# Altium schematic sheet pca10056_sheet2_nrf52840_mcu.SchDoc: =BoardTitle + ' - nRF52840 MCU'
size A3; Organization: Nordic Semiconductor; DocumentNumber: 2; SheetNumber: 2; SheetTotal: 6; CompanyName: Nordic Semiconductor; DocumentSize: A3
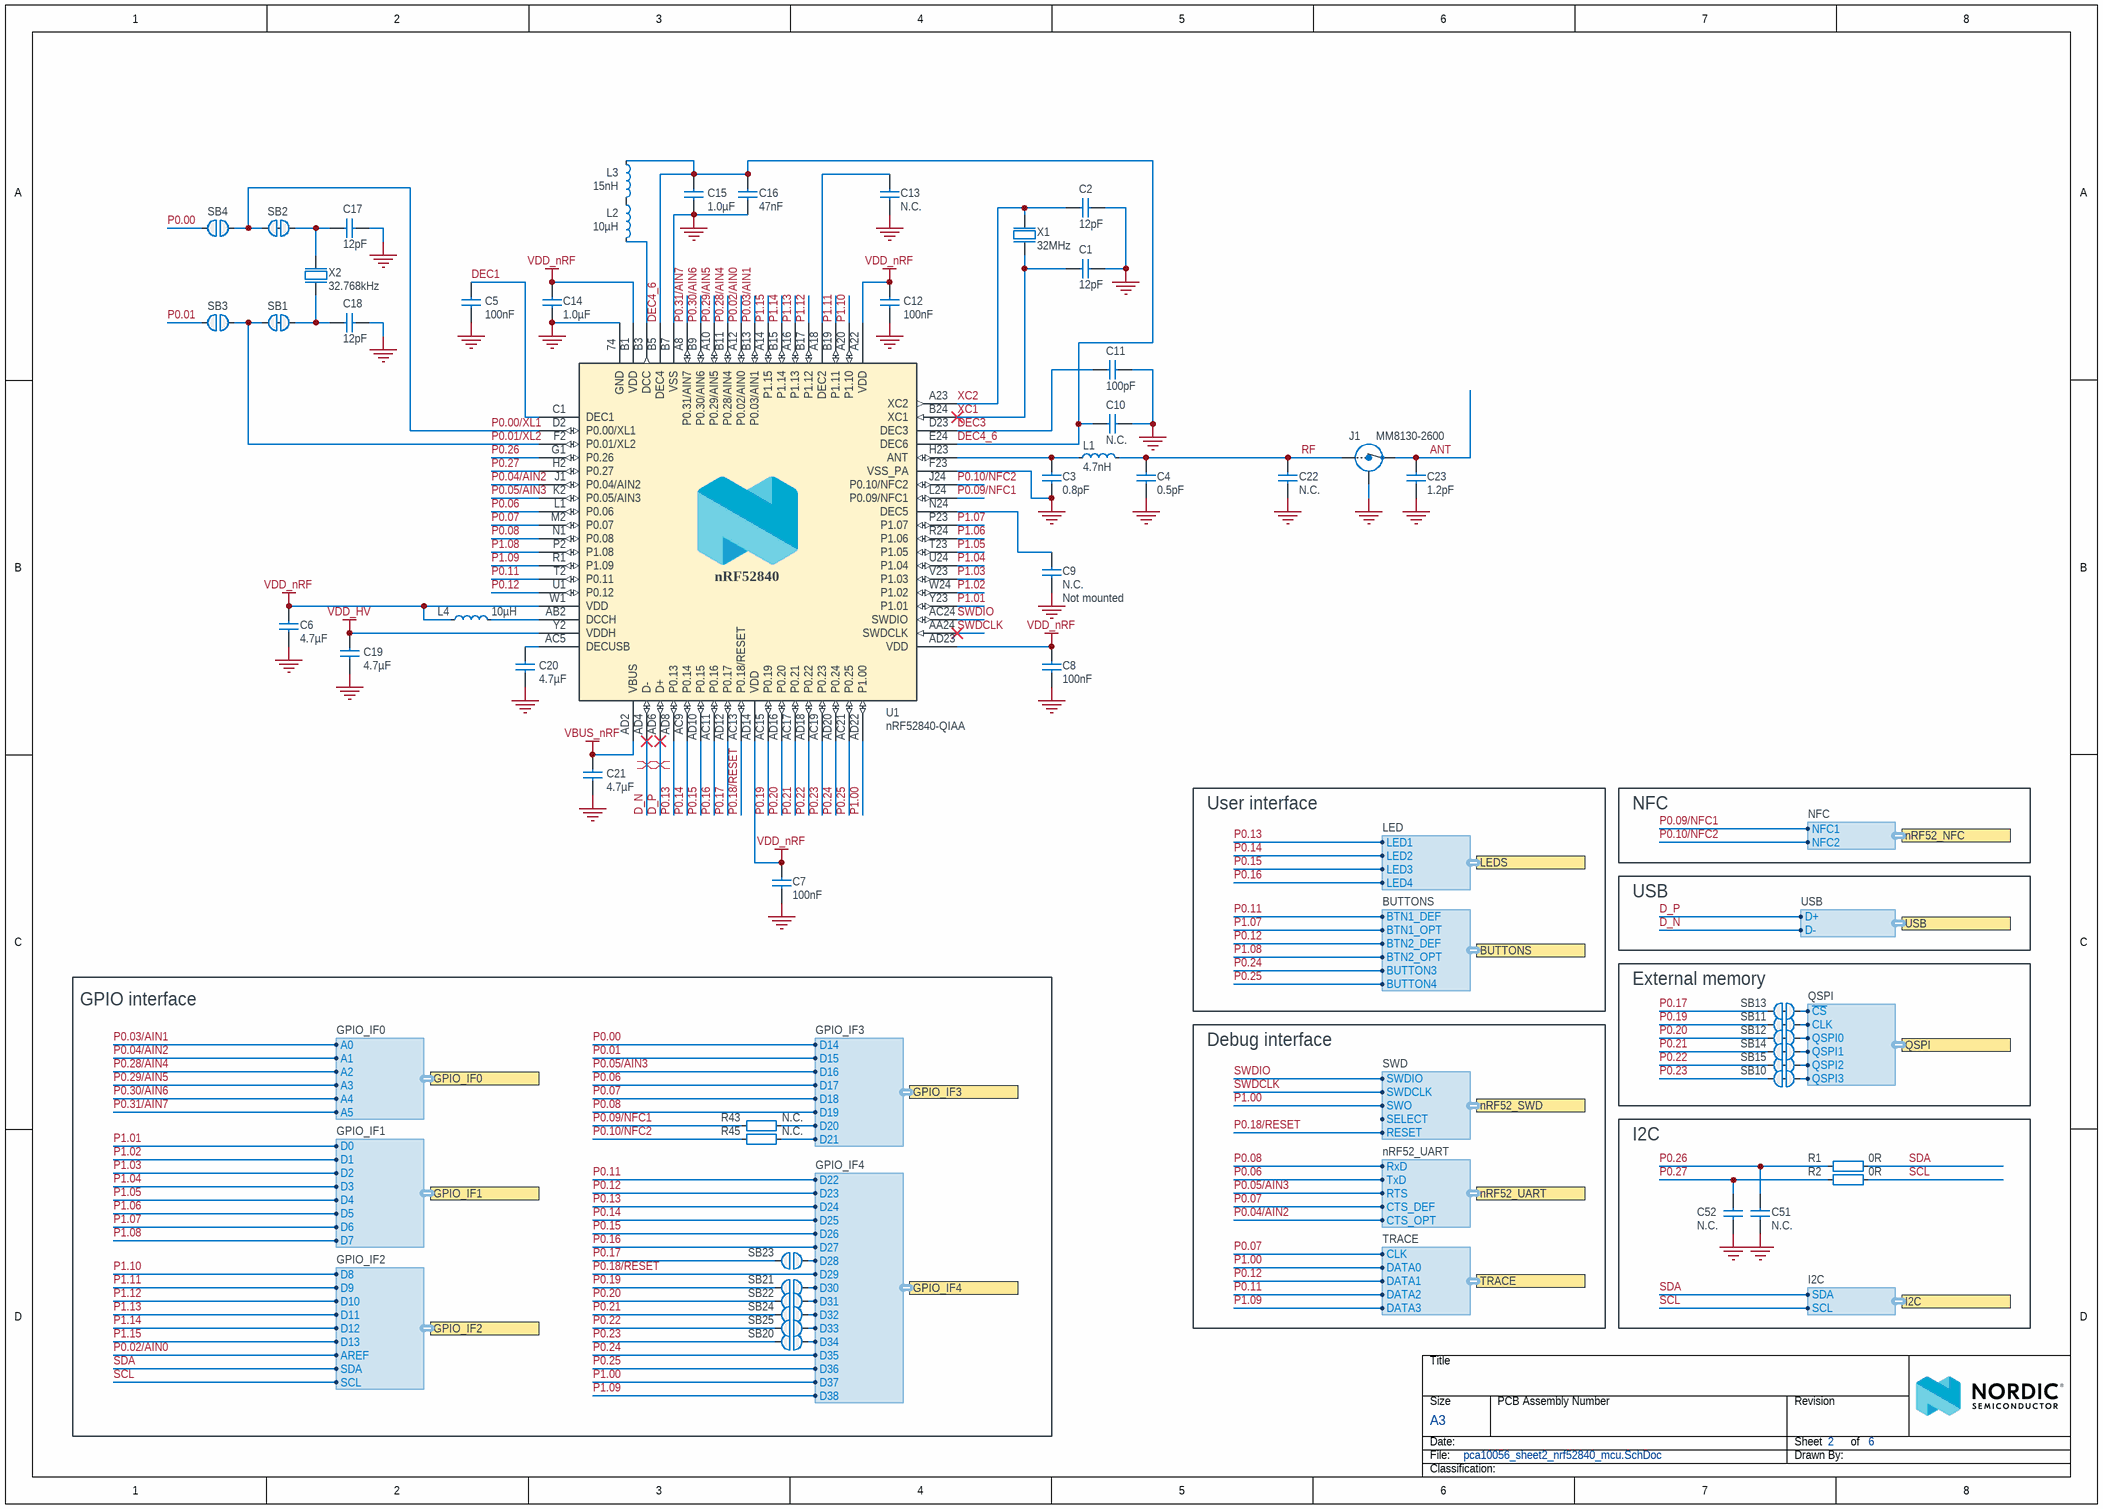
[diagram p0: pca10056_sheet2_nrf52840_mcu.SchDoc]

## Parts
C1  12pF  [CAPC1005X04L]
C2  12pF  [CAPC1005X04L]
C3  0.8pF  [CAPC1005X04L]
C4  0.5pF  [CAPC1005X04L]
C5  100nF  [CAPC1005X04L]
C6  4.7µF  [CAPC1608X06L]
C7  100nF  [CAPC1005X04L]
C8  100nF  [CAPC1005X04L]
C9  N.C.  Assembly: Not mounted  [CAPC1005X04L_NC]
C10  N.C.  [CAPC1005X04L_NC]
C11  100pF  [CAPC1005X04L]
C12  100nF  [CAPC1005X04L]
C13  N.C.  [CAPC1005X04L_NC]
C14  1.0µF  [CAPC1608X06L]
C15  1.0µF  [CAPC1608X06L]
C16  47nF  [CAPC1005X04L]
C17  12pF  [CAPC1005X04L]
C18  12pF  [CAPC1005X04L]
C19  4.7µF  [CAPC1608X06L]
C20  4.7µF  [CAPC1608X06L]
C21  4.7µF  [CAPC1608X06L]
C22  N.C.  [CAPC1005X04L_NC]
C23  1.2pF  [CAPC1005X04L]
C51  N.C.  [CAPC0603X03L_C_NC]
C52  N.C.  [CAPC0603X03L_C_NC]
J1  MM8130-2600  [COAXIAL-SWF]
L1  4.7nH  [INDC1005X04L]
L2  10µH  [INDC1608X06L]
L3  15nH  [INDC1005X04L]
L4  10µH  [INDC1608X06L]
R1  0R  [RESC0603X03L_C]
R2  0R  [RESC0603X03L_C]
R43  N.C.  [RESC1005X04L_NC]
R45  N.C.  [RESC1005X04L_NC]
SB1  Solderbridge  [Solderbridge_Shorted]  (value not drawn)  (net tie, no BOM)
SB2  Solderbridge  [Solderbridge_Shorted]  (value not drawn)  (net tie, no BOM)
SB3  Solderbridge  [Solderbridge]  (value not drawn)  (no BOM)
SB4  Solderbridge  [Solderbridge]  (value not drawn)  (no BOM)
SB10  Solderbridge  [Solderbridge_Shorted]  (value not drawn)  (net tie, no BOM)
SB11  Solderbridge  [Solderbridge_Shorted]  (value not drawn)  (net tie, no BOM)
SB12  Solderbridge  [Solderbridge_Shorted]  (value not drawn)  (net tie, no BOM)
SB13  Solderbridge  [Solderbridge_Shorted]  (value not drawn)  (net tie, no BOM)
SB14  Solderbridge  [Solderbridge_Shorted]  (value not drawn)  (net tie, no BOM)
SB15  Solderbridge  [Solderbridge_Shorted]  (value not drawn)  (net tie, no BOM)
SB20  Solderbridge  [Solderbridge]  (value not drawn)  (no BOM)
SB21  Solderbridge  [Solderbridge]  (value not drawn)  (no BOM)
SB22  Solderbridge  [Solderbridge]  (value not drawn)  (no BOM)
SB23  Solderbridge  [Solderbridge]  (value not drawn)  (no BOM)
SB24  Solderbridge  [Solderbridge]  (value not drawn)  (no BOM)
SB25  Solderbridge  [Solderbridge]  (value not drawn)  (no BOM)
U1  nRF52840-QIAA  [AQFN50P700X700X85_HS-74N]
X1  32MHz  [BT-XTAL_2016]
X2  32.768kHz  [XTAL_3215]

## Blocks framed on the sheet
GPIO interface: R43 R45 SB20-SB25
External memory: SB10-SB15
I2C: C51 C52 R1 R2

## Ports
BUTTONS (harness BUTTONS), GPIO_IF0 (harness GPIO_IF0), GPIO_IF1 (harness GPIO_IF1), GPIO_IF2 (harness GPIO_IF2), GPIO_IF3 (harness GPIO_IF3), GPIO_IF4 (harness GPIO_IF4), I2C (harness I2C), LEDS (harness LED), nRF52_NFC (harness NFC), nRF52_SWD (harness SWD), nRF52_UART (harness nRF52_UART), QSPI (harness QSPI), TRACE (harness TRACE), USB (harness USB)

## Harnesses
BUTTONS: BTN2_OPT, BTN2_DEF, BTN1_OPT, BTN1_DEF, BUTTON3, BUTTON4
QSPI: ~{CS}, QSPI0, CLK, QSPI1, QSPI2, QSPI3
SWD: SWDIO, SWDCLK, SWO, RESET, SELECT
LED: LED4, LED3, LED2, LED1
USB: D+, D-
TRACE: CLK, DATA0, DATA1, DATA3, DATA2
NFC: NFC2, NFC1
GPIO_IF1: D0, D1, D2, D3, D4, D5, D6, D7
GPIO_IF2: D8, D9, D10, D11, D12, D13, AREF, SDA, SCL
GPIO_IF0: A0, A1, A2, A3, A4, A5
GPIO_IF3: D14, D15, D16, D17, D18, D19, D20, D21
I2C: SCL, SDA
GPIO_IF4: D22, D23, D24, D25, D26, D27, D28, D29, D30, D31, D32, D33, D34, D35, D36, D37, D38
nRF52_UART: RTS, CTS_DEF, CTS_OPT, TxD, RxD

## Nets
GND: C1.2 C2.2 C3.1 C4.1 C5.2 C6.2 C7.2 C8.2 C9.2 C10.1 C11.2 C12.2 C13.2 C14.2 C15.1 C16.2 C17.1 C18.1 C19.2 C20.2 C21.2 C22.2 C23.2 C51.1 C52.1 J1.2(Shield) U1.74(GND) U1.B7(VSS) U1.F23(VSS_PA) X1.2(GND) X1.4(GND)
VBUS_nRF: C21.1 U1.AD2(VBUS)
VDD_HV: C19.1 U1.Y2(VDDH)
VDD_nRF: C6.1 C7.1 C8.1 C12.1 C14.1 L4.1 U1.A22(VDD) U1.AD14(VDD) U1.AD23(VDD) U1.B1(VDD) U1.W1(VDD)
ANT: C23.1 J1.3(OUT)
D_N: U1.AD4(D-) ; port USB.D-
D_P: U1.AD6(D+) ; port USB.D+
DEC1: C5.1 U1.C1(DEC1)
DEC3: C11.1 U1.D23(DEC3)
DEC4_6: C10.2 C15.2 C16.1 L3.1 U1.B5(DEC4) U1.E24(DEC6)
P0.00: SB4.2 ; port GPIO_IF3.D14
P0.00/XL1: SB2.2 SB4.1 U1.D2(P0.00/XL1)
P0.01: SB3.2 ; port GPIO_IF3.D15
P0.01/XL2: SB1.2 SB3.1 U1.F2(P0.01/XL2)
P0.02/AIN0: U1.A12(P0.02/AIN0) ; port GPIO_IF2.AREF
P0.03/AIN1: U1.B13(P0.03/AIN1) ; port GPIO_IF0.A0
P0.04/AIN2: U1.J1(P0.04/AIN2) ; port GPIO_IF0.A1, port nRF52_UART.CTS_OPT
P0.05/AIN3: U1.K2(P0.05/AIN3) ; port GPIO_IF3.D16, port nRF52_UART.RTS
P0.06: U1.L1(P0.06) ; port GPIO_IF3.D17, port nRF52_UART.TxD
P0.07: U1.M2(P0.07) ; port TRACE.CLK, port GPIO_IF3.D18, port nRF52_UART.CTS_DEF
P0.08: U1.N1(P0.08) ; port GPIO_IF3.D19, port nRF52_UART.RxD
P0.09/NFC1: R43.2 U1.L24(P0.09/NFC1) ; port nRF52_NFC.NFC1
P0.10/NFC2: R45.2 U1.J24(P0.10/NFC2) ; port nRF52_NFC.NFC2
P0.11: U1.T2(P0.11) ; port BUTTONS.BTN1_DEF, port TRACE.DATA2, port GPIO_IF4.D22
P0.12: U1.U1(P0.12) ; port BUTTONS.BTN2_DEF, port TRACE.DATA1, port GPIO_IF4.D23
P0.13: U1.AD8(P0.13) ; port LEDS.LED1, port GPIO_IF4.D24
P0.14: U1.AC9(P0.14) ; port LEDS.LED2, port GPIO_IF4.D25
P0.15: U1.AD10(P0.15) ; port LEDS.LED3, port GPIO_IF4.D26
P0.16: U1.AC11(P0.16) ; port LEDS.LED4, port GPIO_IF4.D27
P0.17: SB13.1 SB23.1 U1.AD12(P0.17)
P0.18/RESET: U1.AC13(P0.18/RESET) ; port nRF52_SWD.RESET, port GPIO_IF4.D29
P0.19: SB11.1 SB21.1 U1.AC15(P0.19)
P0.20: SB12.1 SB22.1 U1.AD16(P0.20)
P0.21: SB14.1 SB24.1 U1.AC17(P0.21)
P0.22: SB15.1 SB25.1 U1.AD18(P0.22)
P0.23: SB10.1 SB20.1 U1.AC19(P0.23)
P0.24: U1.AD20(P0.24) ; port BUTTONS.BUTTON3, port GPIO_IF4.D35
P0.25: U1.AC21(P0.25) ; port BUTTONS.BUTTON4, port GPIO_IF4.D36
P0.26: C51.2 R1.2 U1.G1(P0.26)
P0.27: C52.2 R2.2 U1.H2(P0.27)
P0.28/AIN4: U1.B11(P0.28/AIN4) ; port GPIO_IF0.A2
P0.29/AIN5: U1.A10(P0.29/AIN5) ; port GPIO_IF0.A3
P0.30/AIN6: U1.B9(P0.30/AIN6) ; port GPIO_IF0.A4
P0.31/AIN7: U1.A8(P0.31/AIN7) ; port GPIO_IF0.A5
P1.00: U1.AD22(P1.00) ; port nRF52_SWD.SWO, port TRACE.DATA0, port GPIO_IF4.D37
P1.01: U1.Y23(P1.01) ; port GPIO_IF1.D0
P1.02: U1.W24(P1.02) ; port GPIO_IF1.D1
P1.03: U1.V23(P1.03) ; port GPIO_IF1.D2
P1.04: U1.U24(P1.04) ; port GPIO_IF1.D3
P1.05: U1.T23(P1.05) ; port GPIO_IF1.D4
P1.06: U1.R24(P1.06) ; port GPIO_IF1.D5
P1.07: U1.P23(P1.07) ; port BUTTONS.BTN1_OPT, port GPIO_IF1.D6
P1.08: U1.P2(P1.08) ; port BUTTONS.BTN2_OPT, port GPIO_IF1.D7
P1.09: U1.R1(P1.09) ; port TRACE.DATA3, port GPIO_IF4.D38
P1.10: U1.A20(P1.10) ; port GPIO_IF2.D8
P1.11: U1.B19(P1.11) ; port GPIO_IF2.D9
P1.12: U1.B17(P1.12) ; port GPIO_IF2.D10
P1.13: U1.A16(P1.13) ; port GPIO_IF2.D11
P1.14: U1.B15(P1.14) ; port GPIO_IF2.D12
P1.15: U1.A14(P1.15) ; port GPIO_IF2.D13
RF: C4.2 C22.1 J1.1(IN) L1.2
SCL: R2.1 ; port GPIO_IF2.SCL, port I2C.SCL
SDA: R1.1 ; port GPIO_IF2.SDA, port I2C.SDA
SWDCLK: U1.AA24(SWDCLK) ; port nRF52_SWD.SWDCLK
SWDIO: U1.AC24(SWDIO) ; port nRF52_SWD.SWDIO
XC1: C1.1 U1.B24(XC1) X1.1(inp)
XC2: C2.1 U1.A23(XC2) X1.3(out)
NetC3_2: C3.2 L1.1 U1.H23(ANT)
NetC9_1: C9.1 U1.N24(DEC5)
NetC13_1: C13.1 U1.A18(DEC2)
NetC17_2: C17.2 SB2.1 X2.1(inp)
NetC18_2: C18.2 SB1.1 X2.2(out)
NetC20_1: C20.1 U1.AC5(DECUSB)
NetL2_1: L2.1 L3.2
NetL2_2: L2.2 U1.B3(DCC)
NetL4_2: L4.2 U1.AB2(DCCH)
NetR43_1: R43.1 ; port GPIO_IF3.D20
NetR45_1: R45.1 ; port GPIO_IF3.D21
NetSB10_2: SB10.2 ; port QSPI.QSPI3
NetSB11_2: SB11.2 ; port QSPI.CLK
NetSB12_2: SB12.2 ; port QSPI.QSPI0
NetSB13_2: SB13.2 ; port QSPI.~{CS}
NetSB14_2: SB14.2 ; port QSPI.QSPI1
NetSB15_2: SB15.2 ; port QSPI.QSPI2
NetSB20_2: SB20.2 ; port GPIO_IF4.D34
NetSB21_2: SB21.2 ; port GPIO_IF4.D30
NetSB22_2: SB22.2 ; port GPIO_IF4.D31
NetSB23_2: SB23.2 ; port GPIO_IF4.D28
NetSB24_2: SB24.2 ; port GPIO_IF4.D32
NetSB25_2: SB25.2 ; port GPIO_IF4.D33

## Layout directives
differential pair: D_N, D_P

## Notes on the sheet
- User interface
- NFC
- USB
- Debug interface

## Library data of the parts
C1 C2 C17 C18 = C0402-12p: Capacitor, NP0, ±2%; Manufacturer: N.A.; Part number IPS: 00000002398; Part number NEMS: 100200137; Note: 50V; Artikkelnr Noca: 20029159; Pad Count: 2; Component Status: Active
C3 = C0402-0.8p: Capacitor, NP0, ±5%; Manufacturer: N.A.; Part number IPS: 00000007782; Part number NEMS: 100200116; Note: 50V; Pad Count: 2; Component Status: Active
C4 = C0402-0.5p: Capacitor, C0G, ±0.05pF, 50V; Manufacturer: N.A.; Part number IPS: 00000004293; Part number NEMS: 100200112; Pad Count: 2; Component Status: Active
C5 C7 C8 C12 = C0402-100n: Capacitor, X7R, ±10%; Manufacturer: N.A.; Part number IPS: 00000005296; Part number NEMS: 100200184; Note: 16V; Artikkelnr Noca: 20039200; Pad Count: 2; Component Status: Active
C6 C20 = C0603-4µ7-6.3V-X7R: Capacitor, X7R, ±10%, 6.3V; Manufacturer: Samsung Electro-Mechanics America; Manufacturer Part Number: CL10B475KQ8NQNC; Part number IPS: 00000002541; Part number Norautron: N.A.; Part number NEMS: 100200350; Artikkelnr Noca: 20039473; Pad Count: 2; Component Status: Active
C9 = C0402-N.C.: Not mounted; Manufacturer: N.A.; Part number NEMS: 100200105; Note: Chip Cap; Pad Count: 2; Component Status: Active
C10 C13 C22 = C0402-N.C.: Not mounted; Manufacturer: N.A.; Part number NEMS: 100200105; Note: Chip Cap; Assembly: Not mounted; Pad Count: 2; Component Status: Active
C11 = C0402-100p: Capacitor, NP0, ±5%; Manufacturer: N.A.; Part number IPS: 00000002361; Part number NEMS: 100200148; Note: 50V; Artikkelnr Noca: 20029135; Pad Count: 2; Component Status: Active
C14 C15 = C0603-1µ0: Capacitor, X7R, ±10%; Manufacturer: N.A.; Part number IPS: 00000000616; Part number Norautron: 262083409; Part number NEMS: 100200271; Note: 16V; Artikkelnr Noca: 20039282; Pad Count: 2; Component Status: Active
C16 = C0402-47n: Capacitor, X7R, ±10%, 25V; Manufacturer: N.A.; Part number IPS: 00000003143; Part number NEMS: 100200180; Note: Chip Cap 10%; Artikkelnr Noca: 20039389; Pad Count: 2; Component Status: Active
C19 C21 = C0603-4µ7-10V-X7S: Capacitor, X7S, ±10%, 10V; Manufacturer: N.A.; Part number IPS: 00000001779; Part number NEMS: 100200351; Artikkelnr Noca: 20030013; Pad Count: 2; Component Status: Active
C23 = C0402-1.2p: Capacitor, NP0, ±0.1pF; Manufacturer: N.A.; Part number IPS: 00000005410; Part number NEMS: 100200119; Note: 50V; Artikkelnr Noca: 20029157; Pad Count: 2; Component Status: Active
C51 C52 = C0201-N.C.: Not mounted; Manufacturer: N.A.; Part number NEMS: 100200001; Assembly: Not mounted; Note: Chip Cap; Pad Count: 2; Component Status: Active
J1 = MM8130-2600: Coaxial Connector with Switch; Manufacturer: Murata; Part number IPS: 00000009955; Part number Norautron: 26030338; Part number NEMS: 100500400; Note: N.A.; Artikkelnr Noca: 55029011; Pad Count: 3; Component Status: Active
L1 = L0402-4n7-LQG15HS4N7B02D: Inductor, 700mA, ±0.1nH, 160mR LQG; Manufacturer: Murata; Part number NEMS: 100300410; Pad Count: 2; Note: High frequency chip inductor ±5%; Artikkelnr Noca: N.A.; Component Status: Active
L2 L4 = L0603-10µ-TDK: Inductor, 250mA, ±20%, 1.05ohm. -55°C ~ 125°C; Manufacturer: TDK Corporation; Manufacturer Part Number: MLZ1608M100WTD25; Part number Norautron: 26521771; Part number NEMS: 100300079; Note: N.A.; Pad Count: 2; Component Status: Active
L3 = L0402-15n-LQG15HS15NJ02D: Inductor, 450mA, ±5%,  0.32ohm; Manufacturer: Murata; Part number NEMS: 100300412; Pad Count: 2; Note: High frequency chip inductor ±5%; Artikkelnr Noca: N.A.; Component Status: Active
R1 R2 = R0201-0R: Resistor, ±5%, 0.05W; Manufacturer: N.A.; Part number IPS: 00000003245; Part number NEMS: 100100001; Note: Chip Res 5%; Pad Count: 2; Component Status: Active
R43 R45 = R0402-N.C.: Not mounted; Manufacturer: N.A.; Part number NEMS: 100100281; Note: Chip Res; Assembly: Not mounted; Pad Count: 2; Component Status: Active
SB1 SB2 SB10-SB15 = Solderbridge Shorted: Shorted Solderbridge; Manufacturer: N.A.; Part number NEMS: 100500459; Pad Count: 2; Component Status: Active; System: Connector
SB3 SB4 SB20-SB25 = Solderbridge: Manufacturer: N.A.; Part number NEMS: 100500458; Pad Count: 2; Component Status: Active; System: Connector
U1 = nRF52840-QIAAF0: Multi-protocol Bluetooth Low Energy, IEEE 802.15.4, ANT and 2.4GHz proprietary system-on-chip; Manufacturer: Nordic Semiconductor; Part number IPS: 80000002377; Part number NEMS: 102000222; Note: N.A.; Pad Count: 73; Component Status: Active
X1 = XTAL_SMD2016_32MHz_8pF_Golledge_MP12308: XTAL SMD 2016, 32MHz, Cl=8pF, Tol: ±10ppm, Stab: ±15ppm, -30°C ~ 85°C, ESR: 50ohm max; Part number NEMS: 101600118,101600041; Note: XTAL SMD 32.000MHz; Artikkelnr Noca: N.A.; Pad Count: 4; Component Status: Active
X2 = XTAL_SMD3215_32.768kHz_9pF_NDK: XTAL SMD 3215, 32.768kHz, 9pF, ±20ppm; Manufacturer: NDK; Manufacturer Part Number: NX3215SA-32.768K-STD-MUA-9; Part number IPS: 00000005419; Part number Norautron: N.A.; Part number NEMS: 101600019; Note: XTAL SMD 32.768kHz; Artikkelnr Noca: 22010049; Pad Count: 2; Component Status: Active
